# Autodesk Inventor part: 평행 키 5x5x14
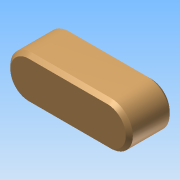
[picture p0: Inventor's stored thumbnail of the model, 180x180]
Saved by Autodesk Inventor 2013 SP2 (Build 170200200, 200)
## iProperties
Created: 2026-07
Part Number: 평행 키 5x5x14
Material: Generic
Document SubType Name: Modeling
Designer: aa
Density: 1 g/cm^3
Author: aa
변환 표준: STEP AP214IS
전처리기: Build: 200, Release: 2013 SP2 Update 6 - Date: Thu 07/17/2014
전송 단위: 밀리미터
불확실성: 0.01
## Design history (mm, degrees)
node "평행 키 5x5x141"
node "솔리드1"
node "기준1"
